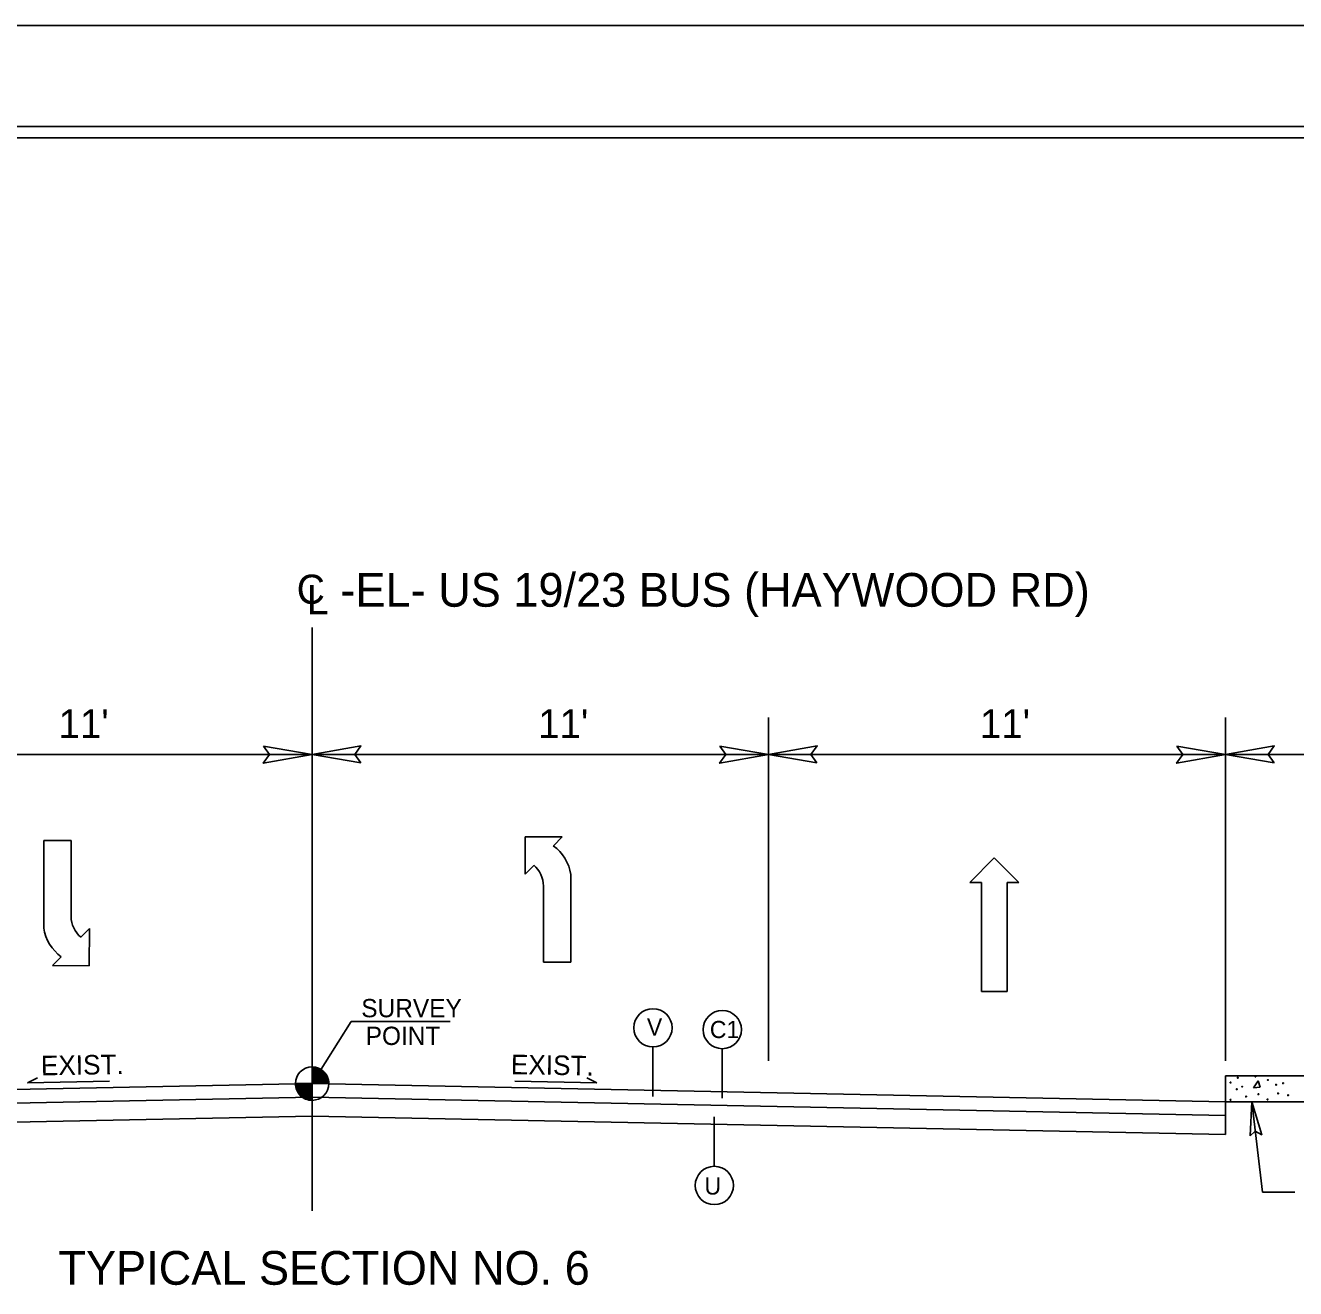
# Model space of a CAD drawing. Extents: x 1022283 to 1026986, y 174822 to 180471.
# Drawn here: x 1023671 to 1024377, y 176870 to 177572 of the extents above; entities that cross this region are included whole.
import ezdxf

# ---------------------------------------------------------------- set-up
doc = ezdxf.new("R2010")
doc.units = 0
for name, color, linetype in [('Default', 7, 'Continuous'), ('Prop Dimension', 7, 'Continuous'), ('Prop Lane Arrow CELL', 7, 'Continuous'), ('Prop Terminator CELL', 7, 'Continuous'), ('Sheet Cutting Line CELL', 7, 'Continuous'), ('Sheet Plot Border Inside CELL', 7, 'Continuous'), ('Sheet Plot Border Outside CELL', 7, 'Continuous'), ('Sheet Typical CELL', 7, 'Continuous'), ('Typical Berm Information CELL', 7, 'Continuous'), ('Typical Curb CELL', 7, 'Continuous'), ('Typical Grade Point Symbol CELL', 7, 'Continuous'), ('Typical ID Circle CELL', 7, 'Continuous'), ('Typical Text Centerline CELL', 7, 'Continuous'), ('Typical Text Grade Point CELL', 7, 'Continuous'), ('Typical Text ID Circle CELL', 7, 'Continuous'), ('Typical Text Label CELL', 7, 'Continuous')]:
    doc.layers.add(name, color=color, linetype=linetype)

# ---------------------------------------------------------------- blocks, each defined once
blk = doc.blocks.new('Lane Arrow Through')
at = {"layer": 'Prop Lane Arrow CELL'}
for p, q in [((-3.15, 1.6), (-3.15, 3.1)), ((-3.15, 3.1), (0, 0)), ((-17.15, 1.6), (-3.15, 1.6)), ((-17.15, -1.7), (-17.15, 1.6)), ((0, 0), (-3.15, -3.2)), ((-3.15, -1.7), (-17.15, -1.7)), ((-3.15, -3.2), (-3.15, -1.7))]:
    blk.add_line(p, q, dxfattribs=at)
blk = doc.blocks.new('Terminator')
at = {"layer": 'Prop Terminator CELL'}
blk.add_lwpolyline([(-9, 1.55), (0, 0), (-9.05, -1.6), (-7.9, 0)], close=True, dxfattribs=at)

msp = doc.modelspace()

# ---------------------------------------------------------------- linework, layer by layer
at = {"layer": 'Default'}
for p, q in [((1024084.14, 176996.93), (1024084.14, 177187.75)), ((1024338.25, 176996.93), (1024338.25, 177187.75)), ((1023576.43, 177167.18), (1023830.54, 177167.18)), ((1023830.54, 177167.18), (1024084.14, 177167.18)), ((1024084.14, 177167.18), (1024338.25, 177167.18)), ((1024338.25, 177167.18), (1024475.62, 177167.18))]:
    msp.add_line(p, q, dxfattribs=at)
at = {"layer": 'Prop Dimension'}
for p, q in [((1023830.54, 177178.3), (1023830.54, 177237.75)), ((1023830.54, 176913.5), (1023830.54, 177178.3)), ((1023852.19, 177018.73), (1023830.54, 176984.29)), ((1023852.19, 177018.73), (1023830.54, 176984.29)), ((1023322.83, 176974.13), (1023830.54, 176984.29)), ((1023322.83, 176974.13), (1023830.54, 176984.29)), ((1024338.25, 176974.13), (1023830.54, 176984.29)), ((1024338.25, 176974.13), (1023830.54, 176984.29)), ((1023322.83, 176966.63), (1023830.54, 176976.79)), ((1023322.83, 176966.63), (1023830.54, 176976.79)), ((1024338.25, 176966.63), (1023830.54, 176976.79)), ((1024338.25, 176966.63), (1023830.54, 176976.79)), ((1024358.75, 176923.88), (1024352.95, 176974.13)), ((1023322.83, 176956.05), (1023830.54, 176966.2)), ((1024338.25, 176956.05), (1023830.54, 176966.2)), ((1024376.9, 176923.88), (1024358.75, 176923.88))]:
    msp.add_line(p, q, dxfattribs=at)
at = {"layer": 'Prop Lane Arrow CELL'}
for p, q in [((1023681.42, 177119.48), (1023681.42, 177070.76)), ((1023696.66, 177119.48), (1023681.42, 177119.48)), ((1023696.66, 177077.23), (1023696.66, 177119.48)), ((1023969.54, 177121.49), (1023948.99, 177121.49)), ((1023948.99, 177121.49), (1023948.99, 177100.71)), ((1023964.69, 177116.41), (1023969.54, 177121.49)), ((1023948.99, 177100.71), (1023953.84, 177105.56)), ((1023974.39, 177051.77), (1023974.39, 177100.48)), ((1023959.15, 177094.02), (1023959.15, 177051.77)), ((1023706.81, 177070.53), (1023701.97, 177065.68)), ((1023706.58, 177049.75), (1023706.81, 177070.53)), ((1023691.11, 177054.83), (1023686.27, 177049.98)), ((1023686.27, 177049.98), (1023706.58, 177049.75)), ((1023959.15, 177051.77), (1023974.39, 177051.77))]:
    msp.add_line(p, q, dxfattribs=at)
for centre, radius, start, end in [((1023950.35, 177096.89), 24.26, 8.67607, 53.98777), ((1023943.97, 177094.13), 15.12, 360, 49.65817), ((1023711.7, 177077.18), 15.12, 180, 229.65817), ((1023705.32, 177074.42), 24.26, 188.67607, 233.98777)]:
    msp.add_arc(centre, radius, start, end, dxfattribs=at)
at = {"layer": 'Prop Terminator CELL'}
for points in [[(1023803.54, 177171.83), (1023830.54, 177167.18), (1023803.39, 177162.38), (1023806.84, 177167.18)], [(1023857.54, 177162.53), (1023830.54, 177167.18), (1023857.69, 177171.98), (1023854.24, 177167.18)], [(1024057.14, 177171.83), (1024084.14, 177167.18), (1024056.99, 177162.38), (1024060.44, 177167.18)], [(1024111.14, 177162.53), (1024084.14, 177167.18), (1024111.29, 177171.98), (1024107.84, 177167.18)], [(1024311.25, 177171.83), (1024338.25, 177167.18), (1024311.1, 177162.38), (1024314.55, 177167.18)], [(1024365.25, 177162.53), (1024338.25, 177167.18), (1024365.4, 177171.98), (1024361.95, 177167.18)]]:
    msp.add_lwpolyline(points, close=True, dxfattribs=at)
at = {"layer": 'Sheet Cutting Line CELL'}
msp.add_line((1026493.22, 177572.45), (1022283.22, 177572.45), dxfattribs=at)
at = {"layer": 'Sheet Plot Border Inside CELL'}
msp.add_lwpolyline([(1026481.97, 177516.33), (1022315.72, 177516.33), (1022315.72, 174878.58), (1026481.97, 174878.58)], close=True, dxfattribs=at)
at = {"layer": 'Sheet Plot Border Outside CELL'}
msp.add_lwpolyline([(1026493.22, 177572.45), (1022283.22, 177572.45), (1022283.22, 174822.45), (1026493.22, 174822.45)], close=True, dxfattribs=at)
at = {"layer": 'Sheet Typical CELL'}
msp.add_lwpolyline([(1026450.72, 177509.95), (1022700.72, 177509.95), (1022700.72, 174884.95), (1026450.72, 174884.95)], close=True, dxfattribs=at)
at = {"layer": 'Typical Berm Information CELL'}
for p, q in [((1023677.89, 176987.5), (1023672.37, 176984.73)), ((1023672.37, 176984.73), (1023717.88, 176985.64)), ((1023988.71, 176984.73), (1023943.2, 176985.64)), ((1023983.19, 176987.5), (1023988.71, 176984.73))]:
    msp.add_line(p, q, dxfattribs=at)
at = {"layer": 'Typical Curb CELL'}
for p, q in [((1024338.25, 176957.65), (1024338.25, 176988.66)), ((1024338.25, 176978.32), (1024338.25, 176988.66)), ((1024338.25, 176978.32), (1024338.25, 176988.66)), ((1024475.62, 176988.66), (1024338.25, 176988.66)), ((1024338.25, 176956.05), (1024338.25, 176988.66)), ((1024338.25, 176957.65), (1024338.25, 176988.66)), ((1024338.25, 176978.32), (1024338.25, 176988.66)), ((1024338.25, 176978.32), (1024338.25, 176988.66)), ((1024475.62, 176988.66), (1024338.25, 176988.66)), ((1024338.25, 176956.05), (1024338.25, 176988.66)), ((1024353.82, 176982.03), (1024356.5, 176985.74)), ((1024353.82, 176982.03), (1024356.5, 176985.74)), ((1024357.57, 176982.22), (1024353.82, 176982.03)), ((1024357.57, 176982.22), (1024353.82, 176982.03)), ((1024356.5, 176985.74), (1024357.57, 176982.22)), ((1024356.5, 176985.74), (1024357.57, 176982.22)), ((1024475.62, 176974.13), (1024338.25, 176974.13))]:
    msp.add_line(p, q, dxfattribs=at)
for centre in [(1024341.11, 176984.85), (1024341.11, 176984.85), (1024345.05, 176987.54), (1024345.05, 176987.54), (1024347.53, 176982.58), (1024347.53, 176982.58), (1024354.9, 176988.24), (1024354.9, 176988.24), (1024361.81, 176986.29), (1024361.81, 176986.29), (1024366.41, 176983.64), (1024366.41, 176983.64), (1024370.31, 176984.52), (1024370.31, 176984.52), (1024341.11, 176975.35), (1024341.11, 176975.35), (1024344.55, 176981.16), (1024344.55, 176981.16), (1024349.7, 176977.1), (1024349.7, 176977.1), (1024356.55, 176978.39), (1024356.55, 176978.39), (1024361.65, 176975.48), (1024361.65, 176975.48), (1024367.47, 176978.86), (1024367.47, 176978.86), (1024373.08, 176977.81), (1024373.08, 176977.81)]:
    msp.add_circle(centre, 0.249, dxfattribs=at)
at = {"layer": 'Typical Grade Point Symbol CELL'}
for p, q in [((1023830.54, 176984.29), (1023830.54, 176993.58)), ((1023830.54, 176984.29), (1023830.54, 176993.58)), ((1023821.24, 176984.29), (1023830.54, 176984.29)), ((1023821.24, 176984.29), (1023830.54, 176984.29)), ((1023830.52, 176974.99), (1023830.54, 176984.29)), ((1023830.54, 176984.29), (1023830.52, 176974.99)), ((1023830.52, 176974.99), (1023830.54, 176984.29)), ((1023830.54, 176984.29), (1023830.52, 176974.99)), ((1023839.83, 176984.29), (1023830.54, 176984.29)), ((1023839.83, 176984.29), (1023830.54, 176984.29))]:
    msp.add_line(p, q, dxfattribs=at)
for points in [[(1023830.62, 176993.58), (1023830.62, 176993.58), (1023830.62, 176984.29)], [(1023830.62, 176993.58), (1023830.62, 176993.58), (1023830.62, 176984.29)], [(1023830.81, 176993.58), (1023830.81, 176984.29)], [(1023830.81, 176993.58), (1023830.81, 176984.29)], [(1023830.99, 176993.56), (1023830.99, 176984.29)], [(1023830.99, 176993.56), (1023830.99, 176984.29)], [(1023831.18, 176993.56), (1023831.18, 176984.29)], [(1023831.18, 176993.56), (1023831.18, 176984.29)], [(1023831.37, 176993.54), (1023831.37, 176984.29)], [(1023831.37, 176993.54), (1023831.37, 176984.29)], [(1023831.55, 176993.52), (1023831.55, 176984.29)], [(1023831.55, 176993.52), (1023831.55, 176984.29)], [(1023831.74, 176993.5), (1023831.74, 176984.29)], [(1023831.74, 176993.5), (1023831.74, 176984.29)], [(1023831.92, 176993.48), (1023831.92, 176984.29)], [(1023831.92, 176993.48), (1023831.92, 176984.29)], [(1023832.11, 176993.46), (1023832.11, 176984.29)], [(1023832.11, 176993.46), (1023832.11, 176984.29)], [(1023832.3, 176993.42), (1023832.3, 176984.29)], [(1023832.3, 176993.42), (1023832.3, 176984.29)], [(1023832.48, 176993.38), (1023832.48, 176984.29)], [(1023832.48, 176993.38), (1023832.48, 176984.29)], [(1023832.67, 176993.34), (1023832.67, 176984.29)], [(1023832.67, 176993.34), (1023832.67, 176984.29)], [(1023832.85, 176993.3), (1023832.85, 176984.29)], [(1023832.85, 176993.3), (1023832.85, 176984.29)], [(1023833.04, 176993.23), (1023833.04, 176984.29)], [(1023833.04, 176993.23), (1023833.04, 176984.29)], [(1023833.22, 176993.19), (1023833.22, 176984.29)], [(1023833.22, 176993.19), (1023833.22, 176984.29)], [(1023833.41, 176993.13), (1023833.41, 176984.29)], [(1023833.41, 176993.13), (1023833.41, 176984.29)], [(1023833.6, 176993.07), (1023833.6, 176984.29)], [(1023833.6, 176993.07), (1023833.6, 176984.29)], [(1023833.78, 176993.01), (1023833.78, 176984.29)], [(1023833.78, 176993.01), (1023833.78, 176984.29)], [(1023833.97, 176992.92), (1023833.97, 176984.29)], [(1023833.97, 176992.92), (1023833.97, 176984.29)], [(1023834.15, 176992.84), (1023834.15, 176984.29)], [(1023834.15, 176992.84), (1023834.15, 176984.29)], [(1023834.34, 176992.76), (1023834.34, 176984.29)], [(1023834.34, 176992.76), (1023834.34, 176984.29)], [(1023834.53, 176992.68), (1023834.53, 176984.29)], [(1023834.53, 176992.68), (1023834.53, 176984.29)], [(1023834.71, 176992.59), (1023834.71, 176984.29)], [(1023834.71, 176992.59), (1023834.71, 176984.29)], [(1023834.9, 176992.49), (1023834.9, 176984.29)], [(1023834.9, 176992.49), (1023834.9, 176984.29)], [(1023835.08, 176992.39), (1023835.08, 176984.29)], [(1023835.08, 176992.39), (1023835.08, 176984.29)], [(1023835.27, 176992.28), (1023835.27, 176984.29)], [(1023835.27, 176992.28), (1023835.27, 176984.29)], [(1023835.46, 176992.18), (1023835.46, 176984.29)], [(1023835.46, 176992.18), (1023835.46, 176984.29)], [(1023835.64, 176992.06), (1023835.64, 176984.29)], [(1023835.64, 176992.06), (1023835.64, 176984.29)], [(1023835.83, 176991.93), (1023835.83, 176984.29)], [(1023835.83, 176991.93), (1023835.83, 176984.29)], [(1023836.01, 176991.79), (1023836.01, 176984.29)], [(1023836.01, 176991.79), (1023836.01, 176984.29)], [(1023836.2, 176991.66), (1023836.2, 176984.29)], [(1023836.2, 176991.66), (1023836.2, 176984.29)], [(1023836.39, 176991.52), (1023836.39, 176984.29)], [(1023836.39, 176991.52), (1023836.39, 176984.29)], [(1023836.57, 176991.35), (1023836.57, 176984.29)], [(1023836.57, 176991.35), (1023836.57, 176984.29)], [(1023836.76, 176991.19), (1023836.76, 176984.29)], [(1023836.76, 176991.19), (1023836.76, 176984.29)], [(1023836.94, 176991.02), (1023836.94, 176984.29)], [(1023836.94, 176991.02), (1023836.94, 176984.29)], [(1023837.13, 176990.84), (1023837.13, 176984.29)], [(1023837.13, 176990.84), (1023837.13, 176984.29)], [(1023837.32, 176990.65), (1023837.32, 176984.29)], [(1023837.32, 176990.65), (1023837.32, 176984.29)], [(1023837.5, 176990.44), (1023837.5, 176984.29)], [(1023837.5, 176990.44), (1023837.5, 176984.29)], [(1023837.69, 176990.22), (1023837.69, 176984.29)], [(1023837.69, 176990.22), (1023837.69, 176984.29)], [(1023837.87, 176989.99), (1023837.87, 176984.29)], [(1023837.87, 176989.99), (1023837.87, 176984.29)], [(1023838.06, 176989.74), (1023838.06, 176984.29)], [(1023838.06, 176989.74), (1023838.06, 176984.29)], [(1023838.25, 176989.47), (1023838.25, 176984.29)], [(1023838.25, 176989.47), (1023838.25, 176984.29)], [(1023838.43, 176989.18), (1023838.43, 176984.29)], [(1023838.43, 176989.18), (1023838.43, 176984.29)], [(1023821.29, 176984.29), (1023821.29, 176983.28)], [(1023821.29, 176984.29), (1023821.29, 176983.28)], [(1023821.47, 176984.29), (1023821.47, 176982.18)], [(1023821.47, 176984.29), (1023821.47, 176982.18)], [(1023821.66, 176984.29), (1023821.66, 176981.52)], [(1023821.66, 176984.29), (1023821.66, 176981.52)], [(1023821.84, 176984.29), (1023821.84, 176980.96)], [(1023821.84, 176984.29), (1023821.84, 176980.96)], [(1023822.03, 176984.29), (1023822.03, 176980.53)], [(1023822.03, 176984.29), (1023822.03, 176980.53)], [(1023822.22, 176984.29), (1023822.22, 176980.14)], [(1023822.22, 176984.29), (1023822.22, 176980.14)], [(1023822.4, 176984.29), (1023822.4, 176979.79)], [(1023822.4, 176984.29), (1023822.4, 176979.79)], [(1023822.59, 176984.29), (1023822.59, 176979.46)], [(1023822.59, 176984.29), (1023822.59, 176979.46)], [(1023822.77, 176984.29), (1023822.77, 176979.17)], [(1023822.77, 176984.29), (1023822.77, 176979.17)], [(1023822.96, 176984.29), (1023822.96, 176978.9)], [(1023822.96, 176984.29), (1023822.96, 176978.9)], [(1023823.15, 176984.29), (1023823.15, 176978.65)], [(1023823.15, 176984.29), (1023823.15, 176978.65)], [(1023823.33, 176984.29), (1023823.33, 176978.42)], [(1023823.33, 176984.29), (1023823.33, 176978.42)], [(1023823.52, 176984.29), (1023823.52, 176978.2)], [(1023823.52, 176984.29), (1023823.52, 176978.2)], [(1023823.7, 176984.29), (1023823.7, 176977.99)], [(1023823.7, 176984.29), (1023823.7, 176977.99)], [(1023823.89, 176984.29), (1023823.89, 176977.78)], [(1023823.89, 176984.29), (1023823.89, 176977.78)], [(1023824.07, 176984.29), (1023824.07, 176977.6)], [(1023824.07, 176984.29), (1023824.07, 176977.6)], [(1023824.26, 176984.29), (1023824.26, 176977.43)], [(1023824.26, 176984.29), (1023824.26, 176977.43)], [(1023824.45, 176984.29), (1023824.45, 176977.27)], [(1023824.45, 176984.29), (1023824.45, 176977.27)], [(1023824.63, 176984.29), (1023824.63, 176977.1)], [(1023824.63, 176984.29), (1023824.63, 176977.1)], [(1023824.82, 176984.29), (1023824.82, 176976.96)], [(1023824.82, 176984.29), (1023824.82, 176976.96)], [(1023825, 176984.29), (1023825, 176976.81)], [(1023825, 176984.29), (1023825, 176976.81)], [(1023825.19, 176984.29), (1023825.19, 176976.69)], [(1023825.19, 176984.29), (1023825.19, 176976.69)], [(1023825.38, 176984.29), (1023825.38, 176976.56)], [(1023825.38, 176984.29), (1023825.38, 176976.56)], [(1023825.56, 176984.29), (1023825.56, 176976.44)], [(1023825.56, 176984.29), (1023825.56, 176976.44)], [(1023825.75, 176984.29), (1023825.75, 176976.32)], [(1023825.75, 176984.29), (1023825.75, 176976.32)], [(1023825.93, 176984.29), (1023825.93, 176976.21)], [(1023825.93, 176984.29), (1023825.93, 176976.21)], [(1023826.12, 176984.29), (1023826.12, 176976.11)], [(1023826.12, 176984.29), (1023826.12, 176976.11)], [(1023826.31, 176984.29), (1023826.31, 176976.01)], [(1023826.31, 176984.29), (1023826.31, 176976.01)], [(1023826.49, 176984.29), (1023826.49, 176975.92)], [(1023826.49, 176984.29), (1023826.49, 176975.92)], [(1023826.68, 176984.29), (1023826.68, 176975.84)], [(1023826.68, 176984.29), (1023826.68, 176975.84)], [(1023826.86, 176984.29), (1023826.86, 176975.76)], [(1023826.86, 176984.29), (1023826.86, 176975.76)], [(1023827.05, 176984.29), (1023827.05, 176975.68)], [(1023827.05, 176984.29), (1023827.05, 176975.68)], [(1023827.23, 176984.29), (1023827.23, 176975.59)], [(1023827.23, 176984.29), (1023827.23, 176975.59)], [(1023827.42, 176984.29), (1023827.42, 176975.53)], [(1023827.42, 176984.29), (1023827.42, 176975.53)], [(1023827.61, 176984.29), (1023827.61, 176975.47)], [(1023827.61, 176984.29), (1023827.61, 176975.47)], [(1023827.79, 176984.29), (1023827.79, 176975.41)], [(1023827.79, 176984.29), (1023827.79, 176975.41)], [(1023827.98, 176984.29), (1023827.98, 176975.37)], [(1023827.98, 176984.29), (1023827.98, 176975.37)], [(1023828.16, 176984.29), (1023828.16, 176975.3)], [(1023828.16, 176984.29), (1023828.16, 176975.3)], [(1023828.35, 176984.29), (1023828.35, 176975.26)], [(1023828.35, 176984.29), (1023828.35, 176975.26)], [(1023828.54, 176984.29), (1023828.54, 176975.22)], [(1023828.54, 176984.29), (1023828.54, 176975.22)], [(1023828.72, 176984.29), (1023828.72, 176975.18)], [(1023828.72, 176984.29), (1023828.72, 176975.18)], [(1023828.91, 176984.29), (1023828.91, 176975.14)], [(1023828.91, 176984.29), (1023828.91, 176975.14)], [(1023829.09, 176984.29), (1023829.09, 176975.12)], [(1023829.09, 176984.29), (1023829.09, 176975.12)], [(1023829.28, 176984.29), (1023829.28, 176975.08)], [(1023829.28, 176984.29), (1023829.28, 176975.08)], [(1023829.47, 176984.29), (1023829.47, 176975.06)], [(1023829.47, 176984.29), (1023829.47, 176975.06)], [(1023829.65, 176984.29), (1023829.65, 176975.04)], [(1023829.65, 176984.29), (1023829.65, 176975.04)], [(1023829.84, 176984.29), (1023829.84, 176975.01)], [(1023829.84, 176984.29), (1023829.84, 176975.01)], [(1023830.02, 176984.29), (1023830.02, 176975.01)], [(1023830.02, 176984.29), (1023830.02, 176975.01)], [(1023830.21, 176984.29), (1023830.21, 176974.99)], [(1023830.21, 176984.29), (1023830.21, 176974.99)], [(1023830.4, 176984.29), (1023830.4, 176974.99), (1023830.4, 176974.99)], [(1023830.4, 176984.29), (1023830.4, 176974.99), (1023830.4, 176974.99)], [(1023838.62, 176988.88), (1023838.62, 176984.29)], [(1023838.62, 176988.88), (1023838.62, 176984.29)], [(1023838.8, 176988.54), (1023838.8, 176984.29)], [(1023838.8, 176988.54), (1023838.8, 176984.29)], [(1023838.99, 176988.15), (1023838.99, 176984.29)], [(1023838.99, 176988.15), (1023838.99, 176984.29)], [(1023839.17, 176987.72), (1023839.17, 176984.29)], [(1023839.17, 176987.72), (1023839.17, 176984.29)], [(1023839.36, 176987.2), (1023839.36, 176984.29)], [(1023839.36, 176987.2), (1023839.36, 176984.29)], [(1023839.55, 176986.56), (1023839.55, 176984.29)], [(1023839.55, 176986.56), (1023839.55, 176984.29)], [(1023839.73, 176985.61), (1023839.73, 176984.29)], [(1023839.73, 176985.61), (1023839.73, 176984.29)]]:
    msp.add_lwpolyline(points, dxfattribs=at)
msp.add_circle((1023830.53, 176984.29), 9.3, dxfattribs=at)
msp.add_circle((1023830.53, 176984.29), 9.3, dxfattribs=at)
for start, end in [(359.99048, 89.99048), (359.99048, 89.99048), (179.99048, 269.99048), (179.99048, 269.99048)]:
    msp.add_arc((1023830.53, 176984.29), 9.3, start, end, dxfattribs=at)
at = {"layer": 'Typical ID Circle CELL'}
for p, q in [((1024019.99, 177004.65), (1024019.99, 176977.12)), ((1024058.52, 177003.68), (1024058.52, 176976.16)), ((1024054.11, 176938.32), (1024054.11, 176965.85))]:
    msp.add_line(p, q, dxfattribs=at)
for centre in [(1024019.99, 177015.29), (1024058.52, 177014.33), (1024054.11, 176927.67)]:
    msp.add_circle(centre, 10.65, dxfattribs=at)
at = {"layer": 'Typical Text Grade Point CELL'}
msp.add_line((1023852.19, 177018.73), (1023907.29, 177018.73), dxfattribs=at)

# ---------------------------------------------------------------- block references
at = {"layer": 'Prop Dimension', "xscale": 2.0767499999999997, "yscale": 2.076749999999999, "rotation": 96.5883266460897}
msp.add_blockref('Terminator', (1024352.95, 176974.13), dxfattribs=at)
at = {"layer": 'Prop Lane Arrow CELL', "xscale": 4.329849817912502, "yscale": 4.329849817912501, "rotation": 90.00000000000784}
msp.add_blockref('Lane Arrow Through', (1024209.59, 177109.75), dxfattribs=at)

# ---------------------------------------------------------------- texts
at = {"layer": 'Prop Dimension'}
for s, height, p in [('-EL- US 19/23 BUS (HAYWOOD RD) ', 18.75, (1023846.26, 177249.35)), ("11'", 16, (1023689.56, 177176.31)), ("11'", 16, (1023956.18, 177176.31)), ("11'", 16, (1024201.73, 177176.31))]:
    msp.add_text(s, height=height, dxfattribs=at).set_placement(p)
at = {"layer": 'Typical Berm Information CELL'}
for rotation, p in [(0.99274, (1023679.85, 176988.84)), (359.00726, (1023940.94, 176989.54))]:
    msp.add_text('EXIST.', height=10.873, rotation=rotation, dxfattribs=at).set_placement(p)
at = {"layer": 'Typical Text Centerline CELL'}
msp.add_text('C', height=16.22, dxfattribs=at).set_placement((1023821.95, 177250.96))
msp.add_text('L', height=16.22, rotation=359.9469, dxfattribs=at).set_placement((1023827.61, 177245.15))
at = {"layer": 'Typical Text Grade Point CELL'}
for s, p in [('SURVEY', (1023857.85, 177021.16)), ('POINT', (1023860.3, 177005.76))]:
    msp.add_text(s, height=10.163, dxfattribs=at).set_placement(p)
at = {"layer": 'Typical Text ID Circle CELL'}
for s, height, p in [('V', 9.53, (1024016.64, 177010.99)), ('C1', 9.534, (1024051.63, 177009.6)), ('U', 9.53, (1024048.66, 176922.61))]:
    msp.add_text(s, height=height, dxfattribs=at).set_placement(p)
at = {"layer": 'Typical Text Label CELL'}
msp.add_text('TYPICAL SECTION NO. 6', height=18.75, dxfattribs=at).set_placement((1023689.52, 176872.49))

doc.saveas('drawing.dxf')
